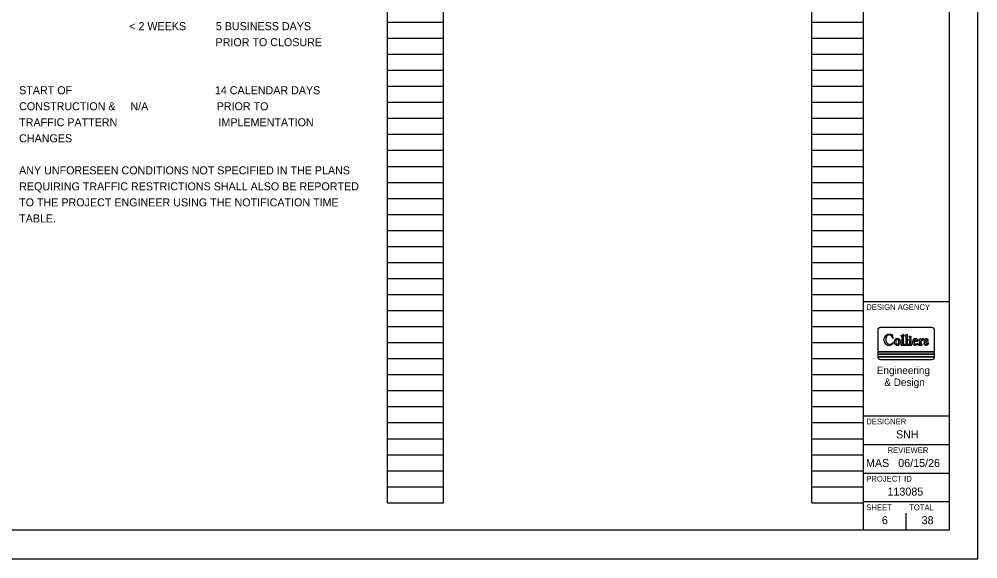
# Model space of a CAD drawing. Extents: x -7.7 to 42.4, y 0 to 36.3.
# Drawn here: x 17.24 to 34, y 0 to 9.43 of the extents above; entities that cross this region are included whole.
import ezdxf

# ---------------------------------------------------------------- set-up
doc = ezdxf.new("R2010")
doc.units = 0
for name, color, linetype in [('SH_Border', 7, 'Continuous'), ('SH_Cut_Line', 7, 'Continuous'), ('SH_Data', 7, 'Continuous'), ('SH_Text', 7, 'Continuous')]:
    doc.layers.add(name, color=color, linetype=linetype)

msp = doc.modelspace()

# ---------------------------------------------------------------- linework, layer by layer
at = {"layer": 'SH_Border'}
for p, q in [((32, 0.5), (32, 21.5)), ((32, 4.5), (33.5, 4.5)), ((32, 2.5), (33.5, 2.5)), ((32, 2), (33.5, 2)), ((32, 1.5), (33.5, 1.5)), ((32, 1), (33.5, 1))]:
    msp.add_line(p, q, dxfattribs=at)
msp.add_lwpolyline([(1.5, 21.5), (33.5, 21.5), (33.5, 0.5), (1.5, 0.5)], close=True, dxfattribs=at)
at = {"layer": 'SH_Cut_Line'}
msp.add_lwpolyline([(0, 0), (34, 0), (34, 22), (0, 22)], close=True, dxfattribs=at)
at = {"layer": 'SH_Data'}
for p, q in [((23.68, 0.98), (23.68, 21.14)), ((24.66, 0.98), (24.66, 21.14)), ((31.1, 0.98), (31.1, 21.14)), ((32, 0.98), (32, 21.14)), ((23.68, 9.38), (24.66, 9.38)), ((31.1, 9.38), (32, 9.38)), ((23.68, 9.1), (24.66, 9.1)), ((31.1, 9.1), (32, 9.1)), ((23.68, 8.82), (24.66, 8.82)), ((31.1, 8.82), (32, 8.82)), ((23.68, 8.54), (24.66, 8.54)), ((31.1, 8.54), (32, 8.54)), ((23.68, 8.26), (24.66, 8.26)), ((31.1, 8.26), (32, 8.26)), ((23.68, 7.98), (24.66, 7.98)), ((31.1, 7.98), (32, 7.98)), ((23.68, 7.7), (24.66, 7.7)), ((31.1, 7.7), (32, 7.7)), ((23.68, 7.42), (24.66, 7.42)), ((31.1, 7.42), (32, 7.42)), ((23.68, 7.14), (24.66, 7.14)), ((31.1, 7.14), (32, 7.14)), ((23.68, 6.86), (24.66, 6.86)), ((31.1, 6.86), (32, 6.86)), ((23.68, 6.58), (24.66, 6.58)), ((31.1, 6.58), (32, 6.58)), ((23.68, 6.3), (24.66, 6.3)), ((31.1, 6.3), (32, 6.3)), ((23.68, 6.02), (24.66, 6.02)), ((31.1, 6.02), (32, 6.02)), ((23.68, 5.74), (24.66, 5.74)), ((31.1, 5.74), (32, 5.74)), ((23.68, 5.46), (24.66, 5.46)), ((31.1, 5.46), (32, 5.46)), ((23.68, 5.18), (24.66, 5.18)), ((31.1, 5.18), (32, 5.18)), ((23.68, 4.9), (24.66, 4.9)), ((31.1, 4.9), (32, 4.9)), ((23.68, 4.62), (24.66, 4.62)), ((31.1, 4.62), (32, 4.62)), ((23.68, 4.34), (24.66, 4.34)), ((31.1, 4.34), (32, 4.34)), ((23.68, 4.06), (24.66, 4.06)), ((31.1, 4.06), (32, 4.06)), ((33.195, 4.043), (32.299, 4.043)), ((32.506, 3.913), (32.507, 3.91)), ((32.511, 3.864), (32.513, 3.859)), ((32.674, 3.881), (32.674, 3.753)), ((32.701, 3.752), (32.701, 3.916)), ((32.741, 3.879), (32.741, 3.751)), ((32.768, 3.751), (32.768, 3.916)), ((23.68, 3.78), (24.66, 3.78)), ((31.1, 3.78), (32, 3.78)), ((32.518, 3.765), (32.522, 3.77)), ((32.596, 3.846), (32.59, 3.846)), ((32.667, 3.745), (32.658, 3.745)), ((32.658, 3.737), (32.845, 3.737)), ((32.734, 3.745), (32.707, 3.745)), ((32.799, 3.745), (32.774, 3.745)), ((32.827, 3.846), (32.791, 3.832)), ((32.805, 3.812), (32.805, 3.751)), ((32.832, 3.749), (32.832, 3.843)), ((32.845, 3.745), (32.836, 3.745)), ((32.886, 3.802), (32.947, 3.802)), ((32.919, 3.81), (32.887, 3.81)), ((32.975, 3.745), (32.968, 3.745)), ((32.968, 3.737), (33.026, 3.737)), ((33, 3.846), (32.969, 3.831)), ((32.969, 3.825), (32.976, 3.821)), ((32.982, 3.81), (32.982, 3.753)), ((33.007, 3.828), (33.006, 3.843)), ((33.01, 3.753), (33.01, 3.807)), ((33.026, 3.745), (33.017, 3.745)), ((33.11, 3.833), (33.125, 3.816)), ((33.132, 3.82), (33.13, 3.835)), ((32.249, 3.533), (33.244, 3.533)), ((33.244, 3.533), (32.249, 3.533)), ((33.245, 3.535), (33.245, 3.575)), ((23.68, 3.5), (24.66, 3.5)), ((31.1, 3.5), (32, 3.5)), ((32.299, 3.485), (33.195, 3.485)), ((32.75, 3.5), (32.75, 3.5)), ((23.68, 3.22), (24.66, 3.22)), ((31.1, 3.22), (32, 3.22)), ((23.68, 2.94), (24.66, 2.94)), ((31.1, 2.94), (32, 2.94)), ((23.68, 2.66), (24.66, 2.66)), ((31.1, 2.66), (32, 2.66)), ((23.68, 2.38), (24.66, 2.38)), ((31.1, 2.38), (32, 2.38)), ((23.68, 2.1), (24.66, 2.1)), ((31.1, 2.1), (32, 2.1)), ((23.68, 1.82), (24.66, 1.82)), ((31.1, 1.82), (32, 1.82)), ((23.68, 1.54), (24.66, 1.54)), ((31.1, 1.54), (32, 1.54)), ((23.68, 1.26), (24.66, 1.26)), ((31.1, 1.26), (32, 1.26)), ((23.68, 0.98), (24.66, 0.98)), ((31.1, 0.98), (32, 0.98)), ((32.375, 0.675), (32.375, 0.675)), ((32.75, 0.5), (32.75, 0.8))]:
    msp.add_line(p, q, dxfattribs=at)
for points in [[(32.249, 3.993), (32.249, 3.617), (33.245, 3.617), (33.245, 3.993)], [(32.521, 3.861), (32.516, 3.886), (32.514, 3.914)], [(33.245, 3.575), (32.249, 3.575), (32.249, 3.535)]]:
    msp.add_lwpolyline(points, dxfattribs=at)
msp.add_lwpolyline([(33.245, 3.617), (32.249, 3.617), (32.249, 3.575), (33.245, 3.575)], close=True, dxfattribs=at)
msp.add_circle((32.815, 3.879), 0.0155, dxfattribs=at)
for centre, radius, start, end in [((32.299, 3.993), 0.0498, 90, 180), ((33.195, 3.993), 0.0498, 0, 90), ((32.456, 3.826), 0.0996, 122.7772, 219.4331), ((32.457, 3.848), 0.0652, 110.6135, 175.9543), ((32.45, 3.835), 0.0884, 54.7696, 122.7772), ((32.45, 3.867), 0.0454, 67.8997, 110.6135), ((32.437, 3.835), 0.0794, 21.2674, 67.8997), ((32.503, 3.91), 0.00381, 234.7696, 0.2433), ((32.51, 3.914), 0.00392, 10.93, 183.8175), ((32.516, 3.862), 0.00427, 213.048, 354.7379), ((32.657, 3.901), 0.00323, 122.5943, 271.3615), ((32.544, 4.221), 0.336, 289.2258, 296.5694), ((32.657, 3.881), 0.0166, 0, 91.3615), ((32.696, 3.916), 0.00466, 0.7043, 112.8976), ((32.724, 3.902), 0.00377, 108.5217, 257.147), ((32.641, 4.168), 0.275, 287.2899, 295.7863), ((32.722, 3.879), 0.019, 0, 85.065), ((32.763, 3.916), 0.00504, 3.9002, 114.2106), ((32.445, 3.817), 0.0857, 219.4331, 285.3506), ((32.526, 3.843), 0.135, 175.9543, 206.5569), ((32.458, 3.81), 0.059, 206.5569, 271.2175), ((32.458, 3.828), 0.0773, 271.2175, 317.7042), ((32.44, 3.834), 0.104, 285.3506, 318.3029), ((32.518, 3.773), 0.00456, 317.5815, 137.7042), ((32.594, 3.79), 0.0573, 155.0154, 195.9836), ((32.593, 3.79), 0.0568, 195.9836, 247.4134), ((32.591, 3.791), 0.0549, 91.4708, 155.0154), ((32.627, 3.79), 0.0628, 159.8672, 197.1421), ((32.617, 3.787), 0.0527, 197.1421, 229.9048), ((32.613, 3.795), 0.0485, 128.4847, 159.8672), ((32.591, 3.784), 0.0512, 247.4134, 292.5866), ((32.592, 3.822), 0.0143, 51.5153, 128.4847), ((32.593, 3.759), 0.0157, 229.9048, 310.0952), ((32.596, 3.791), 0.0547, 22.5432, 90), ((32.572, 3.797), 0.0457, 8.6045, 51.5153), ((32.573, 3.782), 0.0463, 311.5123, 356.3189), ((32.586, 3.797), 0.0652, 292.5866, 340.2533), ((32.532, 3.787), 0.0872, 354.2931, 11.1311), ((32.599, 3.792), 0.0508, 340.2533, 22.5432), ((32.658, 3.741), 0.00412, 90, 270), ((32.667, 3.752), 0.00695, 270, 7.6881), ((32.709, 3.752), 0.00806, 180, 256.9766), ((32.734, 3.751), 0.0065, 270, 3.1556), ((32.775, 3.751), 0.00652, 179.2506, 264.6402), ((32.794, 3.829), 0.00399, 126.9098, 263.7558), ((32.792, 3.812), 0.0128, 0, 83.7558), ((32.799, 3.75), 0.00532, 270, 12.3402), ((32.829, 3.843), 0.00324, 356.2318, 111.3032), ((32.837, 3.749), 0.00485, 180, 266.7746), ((32.845, 3.741), 0.00381, 270, 90), ((32.936, 3.789), 0.0786, 158.9201, 196.7689), ((32.904, 3.78), 0.0455, 196.7689, 259.4625), ((32.906, 3.801), 0.0468, 107.3884, 158.9201), ((32.928, 3.794), 0.0459, 174.8749, 230.9242), ((32.886, 3.798), 0.00367, 90, 174.8749), ((32.917, 3.807), 0.0332, 120.4846, 167.2691), ((32.887, 3.813), 0.00338, 167.2691, 270), ((32.909, 3.792), 0.0557, 72.6116, 107.3884), ((32.906, 3.79), 0.0563, 259.4625, 329.9587), ((32.92, 3.784), 0.0321, 230.9242, 328.1623), ((32.907, 3.823), 0.0144, 42.3189, 120.4846), ((32.901, 3.817), 0.0231, 354.1231, 42.3189), ((32.918, 3.815), 0.00543, 277.2594, 354.1231), ((32.914, 3.809), 0.0381, 357.2625, 72.6116), ((32.946, 3.807), 0.00555, 272.7564, 357.2625), ((32.951, 3.764), 0.00454, 329.9587, 148.1623), ((32.968, 3.741), 0.00381, 91.0116, 270), ((32.971, 3.828), 0.0034, 121.2415, 241.2505), ((32.975, 3.752), 0.00704, 270, 9.7141), ((32.969, 3.81), 0.0136, 0, 59.7444), ((33.002, 3.843), 0.00375, 6.4513, 116.174), ((33.009, 3.828), 0.00158, 185.3907, 323.4477), ((33.094, 3.765), 0.104, 130.2856, 143.4477), ((33.033, 3.807), 0.0235, 141.4263, 180.0327), ((33.018, 3.752), 0.00796, 179.3196, 263.9925), ((33.023, 3.815), 0.0105, 58.8554, 141.4263), ((33.038, 3.831), 0.0179, 49.7144, 130.2856), ((33.026, 3.741), 0.00381, 270, 90), ((33.038, 3.839), 0.018, 238.8554, 310.2856), ((33.041, 3.835), 0.0124, 310.2856, 49.7144), ((33.093, 3.812), 0.0332, 143.4089, 199.3264), ((33.065, 3.768), 0.00485, 20.4198, 193.2731), ((32.948, 3.74), 0.116, 4.8826, 13.2731), ((33.087, 3.81), 0.0263, 199.3264, 242.7351), ((33.077, 3.751), 0.014, 184.8826, 242.2064), ((33.093, 3.812), 0.0334, 105.6066, 143.4089), ((33.118, 3.787), 0.0516, 200.4198, 231.7135), ((33.093, 3.782), 0.0486, 242.2064, 319.0024), ((33.141, 3.915), 0.144, 242.7351, 255.1442), ((33.093, 3.822), 0.0133, 123.6114, 236.3886), ((33.099, 3.79), 0.0558, 61.5074, 105.6066), ((33.099, 3.813), 0.0238, 78.1441, 123.6114), ((33.111, 3.85), 0.0468, 236.3886, 262.0524), ((33.098, 3.761), 0.0185, 231.7135, 325.4966), ((33.101, 3.825), 0.0115, 42.5173, 78.1441), ((33.1, 3.76), 0.016, 325.4966, 75.1442), ((33.099, 3.763), 0.0407, 40.9976, 82.0524), ((33.128, 3.819), 0.00433, 219.7222, 9.1323), ((33.122, 3.833), 0.00795, 16.8946, 61.5074), ((33.107, 3.77), 0.0305, 319.0024, 40.9976), ((32.299, 3.535), 0.0498, 180, 183.1495), ((32.299, 3.535), 0.0498, 183.1495, 270), ((33.195, 3.535), 0.0498, 270, 356.8505), ((33.195, 3.535), 0.0498, 356.8505, 0)]:
    msp.add_arc(centre, radius, start, end, dxfattribs=at)

# ---------------------------------------------------------------- texts
for s, height, p in [('DESIGN AGENCY', 0.1, (32.05, 4.35)), ('Engineering', 0.13025, (32.234, 3.229)), ('& Design', 0.1303, (32.365, 3.022)), ('DESIGNER', 0.1, (32.05, 2.35)), ('SNH', 0.14, (32.569, 2.105)), ('REVIEWER', 0.1, (32.422, 1.85)), ('MAS', 0.14, (32.045, 1.605)), ('06/15/26', 0.14, (32.609, 1.605)), ('PROJECT ID', 0.1, (32.05, 1.35)), ('113085', 0.14, (32.421, 1.105)), ('SHEET', 0.1, (32.05, 0.85)), ('TOTAL', 0.1, (32.8, 0.85)), ('6', 0.14, (32.323, 0.605)), ('38', 0.14, (33.018, 0.605))]:
    msp.add_text(s, height=height, dxfattribs=at).set_placement(p)
at = {"layer": 'SH_Text'}
for s, p in [('                                     < 2 WEEKS          5 BUSINESS DAYS', (17.24, 9.24)), ('                                                                  PRIOR TO CLOSURE', (17.24, 8.96)), ('START OF                                                14 CALENDAR DAYS', (17.24, 8.12)), ('CONSTRUCTION &     N/A                       PRIOR TO', (17.24, 7.84)), ('TRAFFIC PATTERN                                  IMPLEMENTATION', (17.24, 7.56)), ('CHANGES', (17.24, 7.28)), ('ANY UNFORESEEN CONDITIONS NOT SPECIFIED IN THE PLANS', (17.24, 6.72)), ('REQUIRING TRAFFIC RESTRICTIONS SHALL ALSO BE REPORTED', (17.24, 6.44)), ('TO THE PROJECT ENGINEER USING THE NOTIFICATION TIME', (17.24, 6.16)), ('TABLE.', (17.24, 5.88))]:
    msp.add_text(s, height=0.14, dxfattribs=at).set_placement(p)

doc.saveas('drawing.dxf')
